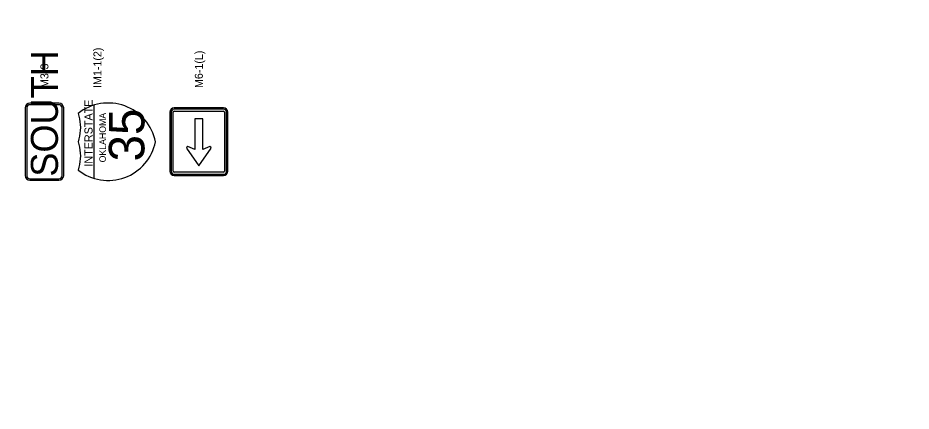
# Model space of a CAD drawing. Extents: x 2135767 to 2151731, y 141839 to 175894.
# Drawn here: x 2141240 to 2141761, y 171851 to 172081 of the extents above; entities that cross this region are included whole.
import ezdxf

# ---------------------------------------------------------------- set-up
doc = ezdxf.new("R2010")
doc.units = 0
for name, color, linetype in [('5', 7, 'Continuous'), ('6', 7, 'Continuous'), ('Default', 7, 'Continuous'), ('PR_Phasing_Detour_1', 7, 'Continuous')]:
    doc.layers.add(name, color=color, linetype=linetype)

msp = doc.modelspace()

# ---------------------------------------------------------------- linework, layer by layer
at = {"layer": '5'}
for p, q in [((2141245.21, 172028.19), (2141245.21, 171988.82)), ((2141263.96, 172030.07), (2141247.09, 172030.07)), ((2141265.84, 171988.82), (2141265.84, 172028.19)), ((2141284.59, 171987.1), (2141284.59, 172029.93)), ((2141359.91, 172028.19), (2141331.14, 172028.19)), ((2141328.65, 172025.7), (2141328.65, 171991.31)), ((2141362.4, 171991.31), (2141362.4, 172025.7)), ((2141247.09, 171986.94), (2141263.96, 171986.94)), ((2141331.14, 171988.82), (2141359.91, 171988.82))]:
    msp.add_line(p, q, dxfattribs=at)
msp.add_lwpolyline([(2141275.21, 171991.97), (2141276.66, 171990.91), (2141278.16, 171989.93), (2141279.73, 171989.06), (2141281.35, 171988.29), (2141283.01, 171987.62), (2141284.72, 171987.06), (2141286.45, 171986.61), (2141288.21, 171986.27), (2141289.99, 171986.05), (2141291.78, 171985.94), (2141293.58, 171985.94), (2141295.36, 171986.05), (2141297.14, 171986.28), (2141298.9, 171986.63), (2141300.64, 171987.08), (2141302.34, 171987.65), (2141304, 171988.32), (2141305.62, 171989.1), (2141307.18, 171989.97), (2141308.69, 171990.95), (2141310.13, 171992.02), (2141311.49, 171993.18), (2141312.79, 171994.42), (2141314, 171995.74), (2141315.12, 171997.14), (2141316.15, 171998.61), (2141317.09, 172000.14), (2141317.92, 172001.73), (2141318.66, 172003.36), (2141319.29, 172005.04), (2141319.8, 172006.76), (2141320.21, 172008.5), (2141319.8, 172010.25), (2141319.29, 172011.97), (2141318.66, 172013.65), (2141317.92, 172015.28), (2141317.09, 172016.87), (2141316.15, 172018.4), (2141315.12, 172019.86), (2141314, 172021.26), (2141312.79, 172022.59), (2141311.49, 172023.83), (2141310.13, 172024.99), (2141308.69, 172026.06), (2141307.18, 172027.03), (2141305.62, 172027.91), (2141304, 172028.69), (2141302.34, 172029.36), (2141300.64, 172029.92), (2141298.9, 172030.38), (2141297.14, 172030.72), (2141295.36, 172030.95), (2141293.58, 172031.07), (2141291.78, 172031.07), (2141289.99, 172030.96), (2141288.21, 172030.73), (2141286.45, 172030.4), (2141284.72, 172029.95), (2141283.01, 172029.39), (2141281.35, 172028.72), (2141279.73, 172027.95), (2141278.16, 172027.07), (2141276.66, 172026.1), (2141275.21, 172025.04), (2141275.66, 172023.42), (2141276.01, 172021.78), (2141276.26, 172020.12), (2141276.41, 172018.45), (2141276.46, 172016.77), (2141276.41, 172015.09), (2141276.26, 172013.42), (2141276.01, 172011.76), (2141275.66, 172010.12), (2141275.21, 172008.5), (2141275.66, 172006.89), (2141276.01, 172005.24), (2141276.26, 172003.59), (2141276.41, 172001.91), (2141276.46, 172000.24), (2141276.41, 171998.56), (2141276.26, 171996.89), (2141276.01, 171995.23), (2141275.66, 171993.59), (2141275.21, 171991.97)], dxfattribs=at)
for centre, radius, start, end in [((2141247.09, 172028.19), 1.87, 90, 180), ((2141263.96, 172028.19), 1.87, 360, 90), ((2141331.14, 172025.7), 2.49, 90, 180), ((2141359.91, 172025.7), 2.49, 360, 90), ((2141331.14, 171991.31), 2.49, 180, 270), ((2141359.91, 171991.31), 2.49, 270, 360), ((2141247.09, 171988.82), 1.87, 180, 270), ((2141263.96, 171988.82), 1.87, 270, 360)]:
    msp.add_arc(centre, radius, start, end, dxfattribs=at)
at = {"layer": '6'}
for p, q in [((2141244.28, 172028.19), (2141244.28, 171988.82)), ((2141263.96, 172031), (2141247.09, 172031)), ((2141266.78, 171988.82), (2141266.78, 172028.19)), ((2141247.09, 171986), (2141263.96, 171986))]:
    msp.add_line(p, q, dxfattribs=at)
for centre, start, end in [((2141247.09, 172028.19), 90, 180), ((2141263.96, 172028.19), 360, 90), ((2141247.09, 171988.82), 180, 270), ((2141263.96, 171988.82), 270, 360)]:
    msp.add_arc(centre, 2.81, start, end, dxfattribs=at)
at = {"layer": 'Default'}
for p, q in [((2141359.91, 172027.49), (2141331.14, 172027.49)), ((2141359.91, 172027.49), (2141331.14, 172027.49)), ((2141329.35, 172025.7), (2141329.35, 171991.31)), ((2141329.35, 172025.7), (2141329.35, 171991.31)), ((2141330.53, 171991.31), (2141330.53, 172025.7)), ((2141330.53, 171991.31), (2141330.53, 172025.7)), ((2141331.14, 172026.32), (2141359.91, 172026.32)), ((2141331.14, 172026.32), (2141359.91, 172026.32)), ((2141347.92, 172021.86), (2141343.13, 172021.86)), ((2141343.13, 172021.86), (2141343.13, 172004.03)), ((2141347.92, 172004.03), (2141347.92, 172021.86)), ((2141360.53, 172025.7), (2141360.53, 171991.31)), ((2141360.53, 172025.7), (2141360.53, 171991.31)), ((2141361.7, 171991.31), (2141361.7, 172025.7)), ((2141361.7, 171991.31), (2141361.7, 172025.7)), ((2141338.34, 172004.83), (2141345.53, 171994.44)), ((2141343.13, 172004.03), (2141339.13, 172005.63)), ((2141345.53, 171994.44), (2141352.72, 172004.83)), ((2141351.92, 172005.63), (2141347.92, 172004.03)), ((2141359.91, 171990.69), (2141331.14, 171990.69)), ((2141359.91, 171990.69), (2141331.14, 171990.69)), ((2141331.14, 171989.52), (2141359.91, 171989.52)), ((2141331.14, 171989.52), (2141359.91, 171989.52))]:
    msp.add_line(p, q, dxfattribs=at)
for points in [[(2141351.92, 172005.63), (2141347.92, 172004.03), (2141347.92, 172021.86), (2141343.13, 172021.86), (2141343.13, 172004.03), (2141339.13, 172005.63)], [(2141338.34, 172004.83), (2141345.53, 171994.44)], [(2141345.53, 171994.44), (2141352.72, 172004.83)]]:
    msp.add_lwpolyline(points, dxfattribs=at)
for centre, radius, start, end in [((2141331.14, 172025.7), 1.79, 90, 180), ((2141331.14, 172025.7), 1.79, 90, 180), ((2141359.91, 172025.7), 1.79, 360, 90), ((2141359.91, 172025.7), 1.79, 360, 90), ((2141331.14, 172025.7), 0.618, 90, 180), ((2141331.14, 172025.7), 0.618, 90, 180), ((2141359.91, 172025.7), 0.618, 360, 90), ((2141359.91, 172025.7), 0.618, 360, 90), ((2141339.13, 172004.83), 0.799, 90, 180), ((2141339.13, 172004.83), 0.799, 90, 180), ((2141351.92, 172004.83), 0.799, 360, 90), ((2141351.92, 172004.83), 0.799, 360, 90), ((2141331.14, 171991.31), 1.79, 180, 270), ((2141331.14, 171991.31), 1.79, 180, 270), ((2141331.14, 171991.31), 0.618, 180, 270), ((2141331.14, 171991.31), 0.618, 180, 270), ((2141359.91, 171991.31), 1.79, 270, 360), ((2141359.91, 171991.31), 0.618, 270, 360), ((2141359.91, 171991.31), 1.79, 270, 360), ((2141359.91, 171991.31), 0.618, 270, 360)]:
    msp.add_arc(centre, radius, start, end, dxfattribs=at)
at = {"layer": 'PR_Phasing_Detour_1'}
msp.add_circle((2140069.54, 171591.41), 4302.23, dxfattribs=at)

# ---------------------------------------------------------------- texts
at = {"layer": 'Default'}
for s, height, p in [('SOUTH', 15.75, (2141263.4, 171988.13)), ('IM1-1(2)', 4.664, (2141288.78, 172039.82)), ('M6-1(L)', 4.664, (2141347.85, 172039.82)), ('M3-3', 4.664, (2141257.85, 172039.82)), ('INTERSTATE', 4.704, (2141283.56, 171993.96)), ('35', 20.7, (2141313.78, 171997.02)), ('OKLAHOMA', 3.812, (2141291.36, 171996.46))]:
    msp.add_text(s, height=height, rotation=90, dxfattribs=at).set_placement(p)

doc.saveas('drawing.dxf')
